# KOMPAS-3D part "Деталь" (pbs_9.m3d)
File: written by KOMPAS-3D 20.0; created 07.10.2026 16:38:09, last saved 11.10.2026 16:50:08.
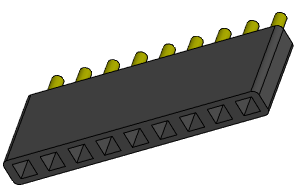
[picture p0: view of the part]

Document properties: Полное имя файла: D:\myProjects\Progect_esp32\box_compas\разъемы\pbs_9.m3d

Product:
- Part/product: Деталь
    Масса: 0.00276261
  - Body: Тело 1
      Масса: 0.00277694

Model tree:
1. Эскиз:1
2. Элемент выдавливания:1
     Расстояние 1 = 8.5
3. Эскиз:2  (with: Элемент выдавливания:1)
4. Элемент выдавливания:2
     Расстояние 1 = 3
5. Массив по сетке:2  (with: Элемент выдавливания:2, Эскиз:2)  (9 pattern instances)
     Шаг 1 = 2.54; Угол раствора = 90
6. Эскиз:3  (with: Элемент выдавливания:1)
7. Элемент выдавливания:3
     Расстояние 2 = 8
8. Массив по сетке:3  (with: Элемент выдавливания:3, Эскиз:3)  (9 pattern instances)
     Шаг 1 = 2.54; Угол раствора = 90; Геометрический массив = 128
9. Скругление:1  (with: Элемент выдавливания:1)
     Радиус = 0.5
